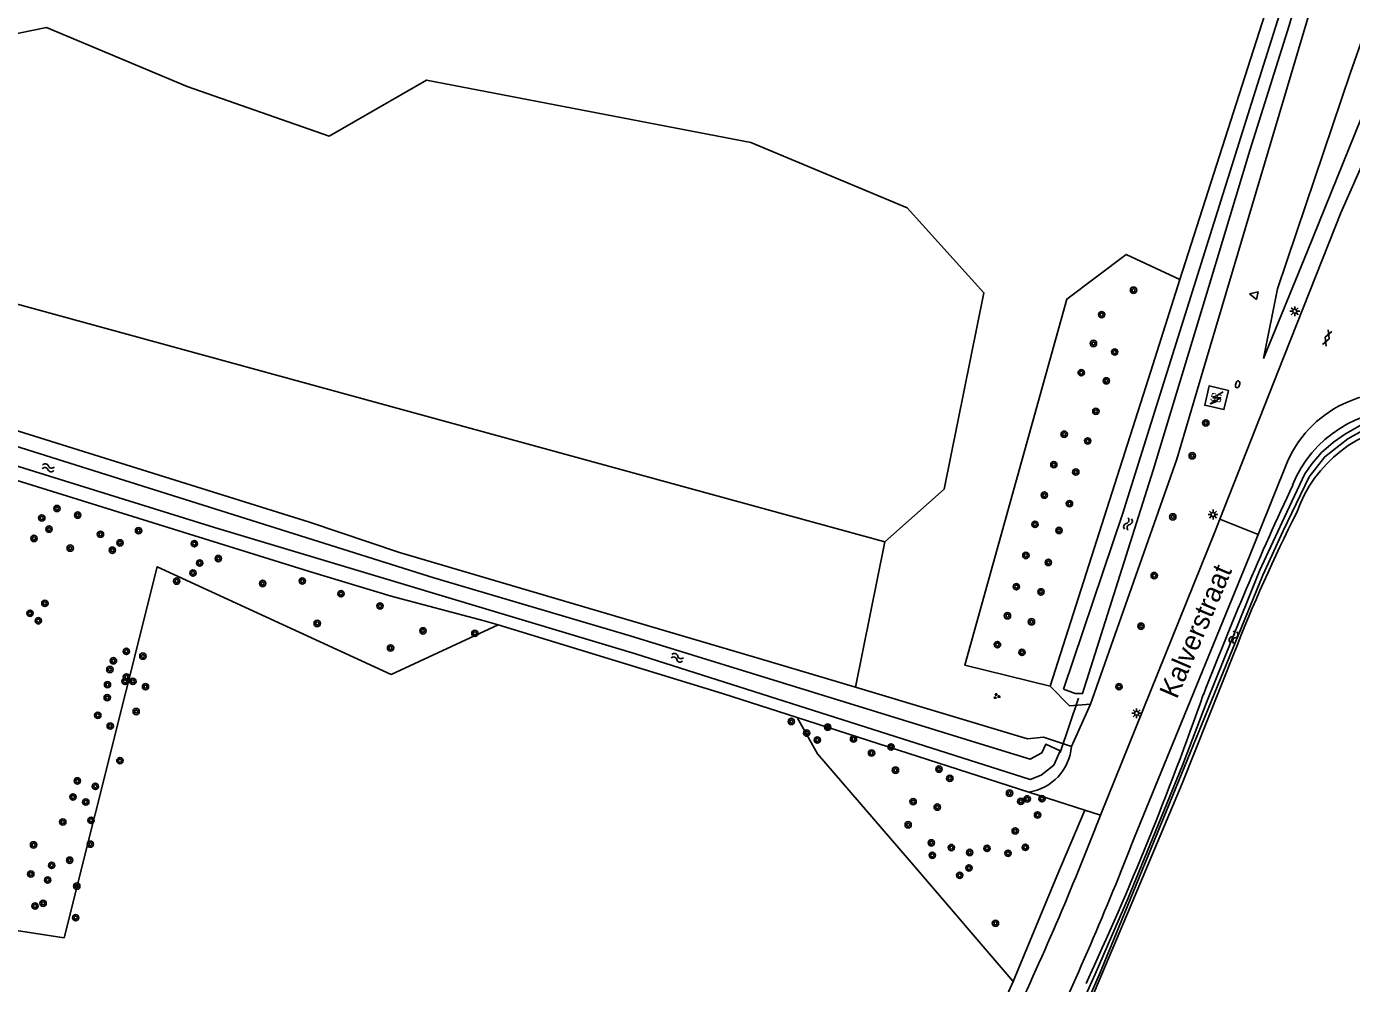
# Model space of a CAD drawing. Extents: x 133000 to 136000, y 400500 to 403500.
# Drawn here: x 133964.2 to 134131.9, y 400922.5 to 401043.6 of the extents above; entities that cross this region are included whole.
import ezdxf

# ---------------------------------------------------------------- set-up
doc = ezdxf.new("R2010")
doc.units = 0
for name, color, linetype in [('gg-afsc-draadraster', 7, 'Continuous'), ('gg-afsc-lijn draadraster', 7, 'Continuous'), ('gg-anno-huisnummerreeks BGT', 7, 'Continuous'), ('gg-anno-openbare ruimte label', 7, 'Continuous'), ('gg-bbg-hoofdgebouw', 7, 'Continuous'), ('gg-knt-BGT kruinlijn', 7, 'Continuous'), ('gg-knt-bovenkant onderkant talud', 7, 'Continuous'), ('gg-knt-verharding', 7, 'Continuous'), ('gg-kntw-bovenkant insteek waterloop', 7, 'Continuous'), ('gg-kntw-waterlijn', 7, 'Continuous'), ('gg-kwrk-duiker nz buis', 7, 'Continuous'), ('gt-grn-groengrens', 7, 'Continuous'), ('gt-grn-weggrens', 7, 'Continuous'), ('gt-symb-boom', 7, 'Continuous'), ('gt-symb-brandkraan', 7, 'Continuous'), ('gt-symb-gesloten verharding', 7, 'Continuous'), ('gt-symb-groenvak', 7, 'Continuous'), ('gt-symb-lichtmast', 7, 'Continuous'), ('gt-symb-trafo symbool', 7, 'Continuous'), ('gt-symb-waterafsluiter', 7, 'Continuous'), ('gt-symb-watersymbool', 7, 'Continuous')]:
    doc.layers.add(name, color=color, linetype=linetype)

# ---------------------------------------------------------------- blocks, each defined once
blk = doc.blocks.new('gt0-BOOM')
at = {"layer": 'gt-symb-boom'}
for radius in [0.4, 0.2]:
    blk.add_circle((0, 0), radius, dxfattribs=at)
blk = doc.blocks.new('gt0-GRVAK')
at = {"layer": 'gt-symb-groenvak'}
for p, q in [((-0.11, 0.19), (-0.23, 0.24)), ((-0.18, 0.15), (0.09, 0.15)), ((-0.09, 0.21), (-0.16, 0.32)), ((-0.05, 0.21), (-0.05, 0.39)), ((0, 0.21), (0.06, 0.32)), ((0.01, 0.19), (0.13, 0.24)), ((0.26, -0.05), (0.2, 0.06)), ((0.3, -0.05), (0.3, 0.13)), ((0.35, -0.05), (0.41, 0.06)), ((-0.25, -0.23), (-0.36, -0.18)), ((-0.32, -0.26), (-0.05, -0.26)), ((-0.23, -0.21), (-0.29, -0.1)), ((-0.18, -0.2), (-0.18, -0.02)), ((-0.14, -0.21), (-0.07, -0.1)), ((-0.12, -0.23), (0, -0.18)), ((0.24, -0.07), (0.12, -0.02)), ((0.17, -0.11), (0.44, -0.11)), ((0.37, -0.07), (0.49, -0.02))]:
    blk.add_line(p, q, dxfattribs=at)
blk = doc.blocks.new('gt0-WA')
at = {"layer": 'gt-symb-watersymbool'}
for centre, start, end in [((-0.32, 0.02), 28.0725, 151.9275), ((0.43, 0.42), 208.0725, 331.9275), ((-0.32, -0.43), 28.0725, 151.9275), ((0.43, -0.03), 208.0725, 331.9275)]:
    blk.add_arc(centre, 0.425, start, end, dxfattribs=at)
blk = doc.blocks.new('gt0-LMAST')
at = {"layer": 'gt-symb-lichtmast'}
for p, q in [((-0.18, 0.17), (-0.45, 0.44)), ((-0.01, 0.25), (-0.01, 0.62)), ((0.17, 0.17), (0.44, 0.44)), ((-0.26, 0), (-0.63, 0)), ((-0.18, -0.18), (-0.45, -0.45)), ((-0.01, -0.25), (-0.01, -0.63)), ((0.44, -0.45), (0.17, -0.18)), ((0.24, 0), (0.62, 0))]:
    blk.add_line(p, q, dxfattribs=at)
blk.add_circle((-0.01, 0), 0.25, dxfattribs=at)
blk = doc.blocks.new('gt0-HSP')
at = {"layer": 'gt-symb-trafo symbool'}
for points in [[(0.77, 0.75), (-0.53, 0), (0.47, 0), (-0.83, -0.75)], [(-0.22, -0.24), (-0.83, -0.75), (-0.08, -0.48)]]:
    blk.add_lwpolyline(points, dxfattribs=at)
blk = doc.blocks.new('gt0-BR')
at = {"layer": 'gt-symb-brandkraan'}
for centre, radius, start, end in [((-0.24, 0), 0.206, 107.5669, 252.4331), ((0.6, -2.66), 3, 106.892, 107.5669), ((0, -0.69), 0.938, 73.108, 106.892), ((-0.6, -2.66), 3, 72.4331, 73.108), ((0.24, 0), 0.206, 287.567, 72.4331), ((0.6, 2.66), 3, 252.4331, 253.108), ((0, 0.69), 0.938, 253.108, 286.8921), ((-0.6, 2.66), 3, 286.8921, 287.567)]:
    blk.add_arc(centre, radius, start, end, dxfattribs=at)
blk = doc.blocks.new('gt0-GESVH1')
at = {"layer": 'gt-symb-gesloten verharding'}
for p, q in [((-0.99, -0.26), (0.01, 0.24)), ((0.01, -0.26), (-0.99, 0.24)), ((0.01, 0.24), (1.01, -0.26)), ((1.01, 0.24), (0.01, -0.26))]:
    blk.add_line(p, q, dxfattribs=at)
blk = doc.blocks.new('gt0-WAFSL')
at = {"layer": 'gt-symb-waterafsluiter'}
for p, q in [((-0.5, -0.33), (0, 0.67)), ((0, 0.67), (0.5, -0.33)), ((0.5, -0.33), (-0.5, -0.33))]:
    blk.add_line(p, q, dxfattribs=at)

msp = doc.modelspace()

# ---------------------------------------------------------------- linework, layer by layer
at = {"layer": 'gg-afsc-draadraster'}
for points in [[(134023.85, 400967.88), (134010.33, 400961.62), (133980.7, 400975.25), (133968.92, 400928.28), (133938.4, 400932.96)], [(134089.07, 400922.74), (134076.69, 400937.16), (134064.31, 400951.57), (134061.73, 400956.15)], [(134038.38, 400839.12), (134047.74, 400852.19), (134063.91, 400877.13), (134078.68, 400901.56), (134087.19, 400918.62), (134089.07, 400922.74)]]:
    msp.add_lwpolyline(points, dxfattribs=at)
at = {"layer": 'gg-afsc-lijn draadraster'}
for points in [[(134023.85, 400967.88), (134010.33, 400961.62), (133980.7, 400975.25), (133968.92, 400928.28), (133938.4, 400932.96)], [(134089.07, 400922.74), (134076.69, 400937.16), (134064.31, 400951.57), (134061.73, 400956.15)], [(134038.38, 400839.12), (134047.74, 400852.19), (134063.91, 400877.13), (134078.68, 400901.56), (134087.19, 400918.62), (134089.07, 400922.74)]]:
    msp.add_lwpolyline(points, dxfattribs=at)
at = {"layer": 'gg-bbg-hoofdgebouw'}
msp.add_lwpolyline([(134116.31, 400997.57), (134115.75, 400995.14), (134113.31, 400995.69), (134113.86, 400998.13), (134116.31, 400997.57)], dxfattribs=at)
at = {"layer": 'gg-knt-BGT kruinlijn'}
for p in [(134135.39, 401037.62), (134120.77, 401001.6)]:
    msp.add_line(p, (134126.26, 401015.13), dxfattribs=at)
at = {"layer": 'gg-knt-bovenkant onderkant talud'}
msp.add_line((134131.76, 401037.79), (134124.93, 401017.57), dxfattribs=at)
at = {"layer": 'gg-knt-verharding'}
for p, q in [((134115.23, 400981.26), (134122.62, 401000)), ((134123.8, 400988.56), (134120.08, 400979.34)), ((134099.68, 400942.72), (134100.11, 400943.79))]:
    msp.add_line(p, q, dxfattribs=at)
for points in [[(134190.67, 401146.32), (134183.06, 401131.29), (134150.39, 401064.88), (134130.54, 401020.06), (134122.62, 401000)], [(134131.76, 401037.79), (134146.27, 401079.03), (134161.92, 401116.17)], [(134124.93, 401017.57), (134122.52, 401010.41), (134120.77, 401001.6)], [(134100.11, 400943.79), (134114.64, 400979.77), (134115.23, 400981.26)], [(134120.08, 400979.34), (134118.97, 400976.58), (134104.43, 400941.03)]]:
    msp.add_lwpolyline(points, dxfattribs=at)
for centre, radius, start, end in [((134137.25, 400982.6), 14.72, 70.0837, 156.0969), ((133754.4, 401076.15), 370.16, 334.3571, 338.8722), ((133701, 401098.91), 433.23, 334.7287, 338.6265)]:
    msp.add_arc(centre, radius, start, end, dxfattribs=at)
at = {"layer": 'gg-kntw-bovenkant insteek waterloop'}
for p, q in [((134129.33, 401054.76), (134113.09, 401000)), ((134120.91, 401045.15), (134110.18, 401011.6)), ((134110.18, 401011.6), (134106.48, 401000)), ((134000, 400974.65), (133918.34, 401000)), ((134000, 400980.88), (133938.87, 401000)), ((134106.48, 401000), (134093.73, 400960.12)), ((134052.25, 400959.21), (134023.85, 400967.88)), ((134069.11, 400959.99), (134056.92, 400963.65)), ((134052.25, 400959.21), (134061.73, 400956.15)), ((134061.73, 400956.15), (134091.04, 400946.71))]:
    msp.add_line(p, q, dxfattribs=at)
for points in [[(134098.87, 400957.86), (134109.78, 400988.85), (134113.09, 401000)], [(134056.92, 400963.65), (134011.39, 400977.04), (134000, 400980.88)], [(134023.85, 400967.88), (134022.1, 400968.42), (134010.33, 400971.53), (134000, 400974.65)], [(134117.04, 400964.36), (134110.46, 400947.82), (134103.55, 400931.34), (134096.59, 400914.88)], [(134096.44, 400952.51), (134092.92, 400953.68), (134090.88, 400953.45), (134069.11, 400959.99)], [(134093.73, 400960.12), (134096.2, 400957.66), (134098.87, 400957.86)]]:
    msp.add_lwpolyline(points, dxfattribs=at)
for centre, radius, start, end in [((134138.43, 400980), 15.06, 86.2463, 158.231), ((134140.86, 400976.64), 16.8, 94.9787, 160.9509), ((134526.03, 400798.77), 442.91, 155.0527, 158.7839), ((134301.64, 400892.56), 198.07, 153.1137, 158.7467), ((133718.33, 401097.94), 418.52, 335.2165, 340.6198), ((134090.08, 400953.02), 6.38, 278.6427, 355.439)]:
    msp.add_arc(centre, radius, start, end, dxfattribs=at)
at = {"layer": 'gg-kntw-waterlijn'}
for points in [[(134095.43, 400959.75), (134102.92, 400981.91), (134119.25, 401033.91), (134125.85, 401054.92), (134128.89, 401061.95), (134130.49, 401069.44), (134131.38, 401076.71), (134131.69, 401089.52), (134132.14, 401108.26)], [(134132.42, 401071.66), (134131.65, 401067.39), (134130.17, 401061.42), (134127.19, 401054.92), (134123.99, 401043.78), (134119.01, 401027.92), (134113.83, 401010.7), (134106.8, 400987.47), (134097.85, 400959.2), (134096.9, 400959.2), (134095.43, 400959.75)], [(134087.08, 400952.17), (134040.56, 400966.52), (134015.71, 400973.85), (133927.28, 401001.71), (133871.64, 401018.87), (133863.8, 401021.29), (133863.12, 401020.59), (133863.51, 401019.69), (133917.54, 401002.13), (133987.97, 400980.23), (134041.26, 400964.23), (134087.25, 400949.58), (134091.22, 400948.32), (134092.62, 400948.87), (134094.21, 400950.11), (134095.03, 400951.95), (134093.19, 400952.77), (134092.71, 400951.69), (134091.2, 400950.88), (134087.08, 400952.17)], [(134095.78, 400915.55), (134099.44, 400923.68), (134103.56, 400933.21), (134108.46, 400945.16), (134110.52, 400950.21), (134113.52, 400958.08), (134118.9, 400971.37), (134120.26, 400974.71), (134123.72, 400982.16), (134125.98, 400987.01), (134126.9, 400988.3), (134128.08, 400989.69), (134129.62, 400991.01), (134131.12, 400992.06), (134132.99, 400993.11)], [(134133.18, 400992.41), (134131.44, 400991.43), (134128.51, 400989.18), (134126.52, 400986.61), (134123.24, 400979.78), (134120.66, 400974.17), (134114.12, 400958.19), (134103.12, 400931.29), (134099.99, 400923.66), (134096.33, 400915.34)]]:
    msp.add_lwpolyline(points, dxfattribs=at)
at = {"layer": 'gg-kwrk-duiker nz buis'}
msp.add_line((134095.02, 400951.73), (134097.32, 400958.63), dxfattribs=at)
at = {"layer": 'gt-grn-groengrens'}
for p, q in [((134072.83, 400978.38), (134069.11, 400959.99)), ((134098.87, 400957.86), (134096.44, 400952.51)), ((134098.15, 400944.42), (134091.04, 400946.71)), ((134100.11, 400943.79), (134098.15, 400944.42))]:
    msp.add_line(p, q, dxfattribs=at)
for points in [[(133939.61, 401028.75), (133947.9, 401039.68), (133966.7, 401043.52), (133984.49, 401036.04), (134002.48, 401029.77), (134014.81, 401036.85), (134055.85, 401028.96), (134075.66, 401020.66), (134085.36, 401009.94), (134080.31, 400985.05), (134072.83, 400978.38)], [(134072.83, 400978.38), (133956.19, 401010.34), (133942.24, 401015.2), (133939.61, 401028.75)], [(134110.18, 401011.6), (134103.35, 401014.79), (134095.87, 401009.13), (134082.94, 400962.8), (134093.73, 400960.12)], [(134089.07, 400922.74), (134094.58, 400936.1), (134098.15, 400944.42)]]:
    msp.add_lwpolyline(points, dxfattribs=at)
at = {"layer": 'gt-grn-weggrens'}
msp.add_line((134120.08, 400979.34), (134115.23, 400981.26), dxfattribs=at)

# ---------------------------------------------------------------- block references
at = {"layer": 'gt-symb-boom'}
for p in [(134104.3, 401010.25), (134100.27, 401007.16), (134099.23, 401003.51), (134101.92, 401002.43), (134097.68, 400999.81), (134100.86, 400998.78), (134099.53, 400994.92), (134113.45, 400993.45), (134095.52, 400992.02), (134098.5, 400991.17), (134111.73, 400989.29), (134094.21, 400988.17), (134096.99, 400987.23), (134093.01, 400984.31), (133968.01, 400982.62), (133970.64, 400981.78), (134096.19, 400983.24), (133966.09, 400981.42), (133967.01, 400980.01), (134091.82, 400980.61), (134109.27, 400981.56), (133965.1, 400978.83), (133973.52, 400979.35), (133975.99, 400978.27), (133978.34, 400979.81), (134094.86, 400979.84), (133969.69, 400977.6), (133975.03, 400977.34), (133985.41, 400978.16), (134090.67, 400976.68), (133986.08, 400975.72), (133988.44, 400976.29), (134093.52, 400975.79), (133983.16, 400973.43), (133985.23, 400974.45), (133999.07, 400973.45), (134106.92, 400974.13), (133994.05, 400973.13), (134003.97, 400971.83), (134089.47, 400972.72), (134092.58, 400972.07), (133966.48, 400970.61), (134008.91, 400970.28), (133964.61, 400969.36), (133965.66, 400968.41), (134088.34, 400969.04), (134091.38, 400968.28), (134000.96, 400968.07), (134014.34, 400967.13), (134020.92, 400966.81), (134105.25, 400967.72), (134010.24, 400964.97), (134087.07, 400965.39), (133975.16, 400963.34), (133976.8, 400964.53), (133978.89, 400963.93), (134090.17, 400964.41), (133974.71, 400962.24), (133974.41, 400960.32), (133976.63, 400960.75), (133976.81, 400961.3), (133977.62, 400960.74), (133979.22, 400960.06), (134102.45, 400960.06), (133974.37, 400958.68), (133978.04, 400956.92), (133973.18, 400956.44), (133974.75, 400955.08), (134060.98, 400955.66), (134065.59, 400954.94), (134062.91, 400954.19), (134064.27, 400953.31), (134068.85, 400953.44), (134071.13, 400951.67), (134073.6, 400952.44), (133975.98, 400950.71), (133970.6, 400948.14), (134074.16, 400949.49), (134079.67, 400949.63), (134081.04, 400948.46), (133972.87, 400947.45), (134088.6, 400946.59), (133970.04, 400946.11), (133971.66, 400945.46), (134076.4, 400945.52), (134079.45, 400944.82), (134090.03, 400945.55), (134090.84, 400945.86), (134092.71, 400945.88), (133972.33, 400943.14), (134092.15, 400943.83), (133968.75, 400942.94), (134075.77, 400942.58), (134089.32, 400941.8), (133965.05, 400940.04), (133972.23, 400940.13), (134078.7, 400940.3), (134081.23, 400939.7), (134090.61, 400939.72), (133969.62, 400938.1), (134078.82, 400938.72), (134083.56, 400939.08), (134085.75, 400939.6), (134088.41, 400938.98), (133964.7, 400936.35), (133967.34, 400937.45), (134083.46, 400937.12), (133966.84, 400935.59), (133970.52, 400934.82), (134082.3, 400936.19), (133965.24, 400932.3), (133966.26, 400932.65), (133970.38, 400930.82), (134086.82, 400930.11)]:
    msp.add_blockref('gt0-BOOM', p, dxfattribs=at)
at = {"layer": 'gt-symb-brandkraan', "rotation": -103.29958432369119}
msp.add_blockref('gt0-BR', (134117.48, 400998.34), dxfattribs=at)
at = {"layer": 'gt-symb-gesloten verharding', "rotation": 68.46463512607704}
msp.add_blockref('gt0-GESVH1', (134128.8, 401004.2), dxfattribs=at)
at = {"layer": 'gt-symb-groenvak'}
msp.add_blockref('gt0-GRVAK', (134086.96, 400958.86), dxfattribs=at)
at = {"layer": 'gt-symb-lichtmast'}
for p in [(134124.72, 401007.59), (134114.37, 400981.86), (134104.7, 400956.7)]:
    msp.add_blockref('gt0-LMAST', p, dxfattribs=at)
at = {"layer": 'gt-symb-trafo symbool'}
msp.add_blockref('gt0-HSP', (134114.87, 400996.63), dxfattribs=at)
at = {"layer": 'gt-symb-waterafsluiter', "rotation": 76.99249520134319}
msp.add_blockref('gt0-WAFSL', (134119.65, 401009.63), dxfattribs=at)
at = {"layer": 'gt-symb-watersymbool'}
for p, rotation in [((133966.85, 400987.78), -7.587069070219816), ((134103.58, 400980.62), 73.61369433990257), ((134116.94, 400966.28), 73.61369433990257), ((134046.48, 400963.74), -15.425970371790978)]:
    msp.add_blockref('gt0-WA', p, dxfattribs=dict(at, rotation=rotation))

# ---------------------------------------------------------------- texts
at = {"layer": 'gg-anno-huisnummerreeks BGT'}
msp.add_text('55', height=1, rotation=347.3, dxfattribs=at).set_placement((134113.93, 400996.32))
at = {"layer": 'gg-anno-openbare ruimte label'}
msp.add_text('Kalverstraat', height=2.5, rotation=66.8, dxfattribs=at).set_placement((134109.78, 400958.41))

doc.saveas('drawing.dxf')
